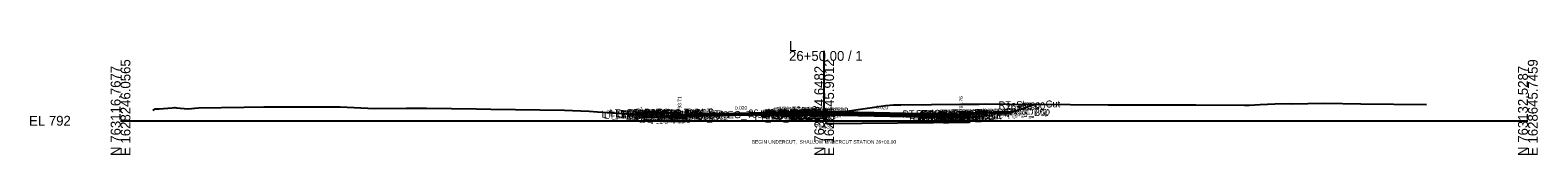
# Model space of a CAD drawing. Extents: x -26 to 4403, y -510 to 9556.
# Drawn here: x 974.3 to 1402.8, y 6490.3 to 6522.6 of the extents above; entities that cross this region are included whole.
import ezdxf

# ---------------------------------------------------------------- set-up
doc = ezdxf.new("R2010")
doc.units = 0
for name, color, linetype in [('Default', 7, 'Continuous'), ('Exist CMT Pavement', 7, 'Continuous'), ('Exist Cross Section Cell', 7, 'Continuous'), ('Exist XS Center Line Elevation Label', 7, 'Continuous'), ('Exist XS Ground Line', 7, 'Continuous'), ('Prop CMT Conc Surface', 7, 'Continuous'), ('Prop CMT Concrete Structures', 7, 'Continuous'), ('Prop CMT Pvmt Course 1', 7, 'Continuous'), ('Prop CMT Pvmt Course 1 CG', 7, 'Continuous'), ('Prop CMT Pvmt Course 1 Wedge', 7, 'Continuous'), ('Prop CMT Pvmt Course 2', 7, 'Continuous'), ('Prop CMT Pvmt Course 2 Wedge', 7, 'Continuous'), ('Prop CMT Pvmt Course 3', 7, 'Continuous'), ('Prop CMT Pvmt Course 3 Wedge', 7, 'Continuous'), ('Prop CMT Pvmt Surface', 7, 'Continuous'), ('Prop CMT Pvmt Wedge Surface 1', 7, 'Continuous'), ('Prop CMT Pvmt Wedge Surface 2', 7, 'Continuous'), ('Prop CMT Pvmt Wedge Surface 3', 7, 'Continuous'), ('Prop CMT Shallow Undercut', 7, 'Continuous'), ('Prop CMT Shallow Undercut Boundary', 7, 'Continuous'), ('Prop CMT Slope Grass', 7, 'Continuous'), ('Prop CMT Subgrade Earthwork', 7, 'Continuous'), ('Prop CMT Undercut Boundary', 7, 'Continuous'), ('Prop XS Hydro Elevations', 7, 'Continuous'), ('Prop XS SE Text', 7, 'Continuous'), ('Prop XS Side Slope Text', 7, 'Continuous'), ('Prop XSC Text', 7, 'Continuous'), ('Scratch_Level_0', 7, 'Continuous')]:
    doc.layers.add(name, color=color, linetype=linetype)

msp = doc.modelspace()

# ---------------------------------------------------------------- linework, layer by layer
at = {"layer": 'Exist CMT Pavement'}
msp.add_lwpolyline([(1160.9, 6501.43), (1171.19, 6501.86), (1176.98, 6501.75), (1181.31, 6501.69), (1185.62, 6501.51), (1189.99, 6501.34), (1190.57, 6501.32)], dxfattribs=at)
at = {"layer": 'Exist Cross Section Cell'}
for p, q in [((1200, 6500), (1200, 6519.84)), ((1000, 6500), (1200, 6500)), ((1200, 6500), (1400, 6500))]:
    msp.add_line(p, q, dxfattribs=at)
at = {"layer": 'Exist XS Ground Line'}
msp.add_lwpolyline([(1009.14, 6503.05), (1009.88, 6503.44), (1010.97, 6503.42), (1014.63, 6503.65), (1015.4, 6503.76), (1015.95, 6503.72), (1019.13, 6503.42), (1022.12, 6503.7), (1035.13, 6503.85), (1040.71, 6504.01), (1057.75, 6504.01), (1060.01, 6504), (1062.44, 6503.92), (1072.29, 6503.51), (1081.25, 6503.56), (1082.14, 6503.59), (1086.94, 6503.54), (1101.16, 6503.37), (1105.24, 6503.3), (1126.19, 6503.01), (1128.43, 6502.93), (1133.2, 6502.71), (1135.52, 6502.55), (1146.59, 6501.77), (1149.27, 6501.42), (1149.72, 6500.98), (1158.89, 6501.34), (1171.19, 6501.86), (1176.98, 6501.75), (1181.31, 6501.69), (1185.62, 6501.51), (1189.99, 6501.34), (1190.57, 6501.32), (1192.61, 6501.05), (1193.25, 6501.57), (1198.86, 6502.27), (1199.46, 6502.35), (1200, 6502.35), (1204.46, 6502.35), (1205.75, 6502.6), (1217.56, 6504.35), (1219.69, 6504.53), (1221.74, 6504.54), (1239.22, 6504.74), (1241.76, 6504.75), (1242.36, 6504.75), (1244.05, 6504.76), (1245.79, 6504.77), (1257.7, 6504.62), (1259.18, 6504.69), (1280.69, 6504.57), (1282.01, 6504.57), (1300, 6504.53), (1301.33, 6504.53), (1305.67, 6504.51), (1319.5, 6504.44), (1320.84, 6504.43), (1323.87, 6504.61), (1328.1, 6504.78), (1332.19, 6504.89), (1332.7, 6504.83), (1342.22, 6504.96), (1352.54, 6504.84), (1371.16, 6504.62)], dxfattribs=at)
at = {"layer": 'Prop CMT Conc Surface'}
for points in [[(1154.38, 6502.3), (1149.38, 6502.4)], [(1154.38, 6502.3), (1154.38, 6502.3)], [(1158.89, 6501.71), (1158.89, 6502.21), (1158.39, 6502.21)], [(1160.89, 6501.83), (1158.89, 6501.71)], [(1236.89, 6501.88), (1238.89, 6501.76)], [(1238.89, 6501.76), (1238.89, 6502.26), (1239.39, 6502.26)], [(1248.02, 6502.44), (1253.01, 6502.54)]]:
    msp.add_lwpolyline(points, dxfattribs=at)
at = {"layer": 'Prop CMT Concrete Structures'}
for points in [[(1149.38, 6502.4), (1154.38, 6502.3)], [(1149.38, 6502.07), (1149.38, 6502.4)], [(1154.38, 6501.97), (1149.38, 6502.07)], [(1154.38, 6502.3), (1154.38, 6502.3)], [(1160.89, 6501.83), (1158.89, 6501.71), (1158.89, 6502.21), (1158.39, 6502.21)], [(1158.39, 6502.21), (1158.39, 6501.2), (1160.89, 6501.25)], [(1160.89, 6501.25), (1160.89, 6501.83)], [(1196, 6502.7), (1195.99, 6502.86), (1195.24, 6503.11), (1194, 6503.14), (1192.76, 6502.87), (1192.01, 6502.62), (1192, 6502.46)], [(1192, 6502.46), (1196, 6502.7)], [(1236.89, 6501.88), (1238.89, 6501.76), (1238.89, 6502.26), (1239.39, 6502.26)], [(1239.39, 6502.26), (1239.39, 6501.24), (1236.89, 6501.29)], [(1236.89, 6501.29), (1236.89, 6501.88)], [(1253.01, 6502.54), (1248.02, 6502.44)], [(1248.02, 6502.44), (1248.02, 6502.11)], [(1248.02, 6502.11), (1253.01, 6502.21)], [(1253.01, 6502.21), (1253.01, 6502.54)]]:
    msp.add_lwpolyline(points, dxfattribs=at)
msp.add_lwpolyline([(1154.38, 6502.3), (1154.38, 6501.97), (1154.38, 6501.97)], close=True, dxfattribs=at)
at = {"layer": 'Prop CMT Pvmt Course 1'}
for points in [[(1192, 6502.46), (1160.89, 6501.83)], [(1160.89, 6501.71), (1192, 6502.33)], [(1160.89, 6501.83), (1160.89, 6501.58)], [(1160.89, 6501.58), (1160.89, 6501.71)], [(1160.89, 6501.58), (1160.89, 6501.58)], [(1192, 6502.46), (1196, 6502.7)], [(1192, 6502.21), (1192, 6502.46)], [(1192, 6502.21), (1192, 6502.46)], [(1196, 6502.45), (1192, 6502.21)], [(1192, 6502.33), (1192, 6502.21), (1192, 6502.21)], [(1196, 6502.7), (1196, 6502.45)], [(1196, 6502.7), (1236.89, 6501.88)], [(1196, 6502.45), (1196, 6502.7)], [(1236.89, 6501.63), (1196, 6502.45)], [(1236.89, 6501.88), (1236.89, 6501.63)]]:
    msp.add_lwpolyline(points, dxfattribs=at)
msp.add_lwpolyline([(1196, 6502.45), (1196, 6502.57), (1196, 6502.57), (1196, 6502.45)], close=True, dxfattribs=at)
at = {"layer": 'Prop CMT Pvmt Course 1 CG'}
for points in [[(1160.89, 6501.25), (1157.89, 6501.19), (1157.55, 6500.85)], [(1157.55, 6500.85), (1160.89, 6500.92)], [(1160.89, 6500.92), (1160.89, 6501.25)], [(1236.89, 6501.29), (1239.89, 6501.23), (1240.23, 6500.89)], [(1236.89, 6500.96), (1236.89, 6501.29)], [(1240.23, 6500.89), (1236.89, 6500.96)]]:
    msp.add_lwpolyline(points, dxfattribs=at)
at = {"layer": 'Prop CMT Pvmt Course 1 Wedge'}
for points in [[(1160.89, 6501.71), (1171.19, 6501.91), (1176.98, 6502.03), (1181.31, 6502.12), (1185.62, 6502.2), (1189.99, 6502.29), (1190.57, 6502.3), (1190.7, 6502.3), (1192, 6502.33)], [(1192, 6502.21), (1190.7, 6502.18), (1190.57, 6502.18), (1189.99, 6502.16), (1185.62, 6502.08), (1181.31, 6501.99), (1176.98, 6501.9), (1173.05, 6501.83), (1171.19, 6501.86), (1167.98, 6501.72), (1160.89, 6501.58)], [(1160.89, 6501.58), (1160.89, 6501.71)], [(1192, 6502.33), (1192, 6502.21)]]:
    msp.add_lwpolyline(points, dxfattribs=at)
at = {"layer": 'Prop CMT Pvmt Course 2'}
for points in [[(1160.89, 6501.25), (1160.89, 6501.58)], [(1160.89, 6501.58), (1160.89, 6501.58)], [(1160.89, 6501.58), (1160.89, 6501.25)], [(1160.89, 6501.25), (1160.89, 6501.25)], [(1192, 6502.21), (1196, 6502.45)], [(1192, 6501.87), (1192, 6502.21)], [(1196, 6502.11), (1192, 6501.87)], [(1196, 6502.45), (1196, 6502.11)], [(1196, 6502.11), (1196, 6502.45)], [(1196, 6502.45), (1236.89, 6501.63)], [(1236.89, 6501.29), (1196, 6502.11)], [(1236.89, 6501.63), (1236.89, 6501.29)]]:
    msp.add_lwpolyline(points, dxfattribs=at)
at = {"layer": 'Prop CMT Pvmt Course 2 Wedge'}
for points in [[(1160.89, 6501.58), (1167.98, 6501.72)], [(1167.98, 6501.72), (1160.89, 6501.43)], [(1160.89, 6501.43), (1160.89, 6501.58)], [(1173.05, 6501.83), (1176.98, 6501.9)], [(1192, 6501.87), (1190.7, 6501.85), (1190.57, 6501.84), (1189.99, 6501.83), (1185.62, 6501.74), (1181.81, 6501.67), (1181.31, 6501.69), (1176.98, 6501.75), (1173.05, 6501.83)], [(1176.98, 6501.9), (1181.31, 6501.99), (1185.62, 6502.08), (1189.99, 6502.16), (1190.57, 6502.18), (1190.7, 6502.18), (1192, 6502.21)], [(1192, 6502.21), (1192, 6501.87)]]:
    msp.add_lwpolyline(points, dxfattribs=at)
at = {"layer": 'Prop CMT Pvmt Course 3'}
for points in [[(1160.89, 6501.25), (1160.89, 6501.25)], [(1160.89, 6501.25), (1160.89, 6500.92)], [(1160.89, 6500.92), (1160.89, 6501.25)], [(1160.89, 6500.92), (1160.89, 6500.92)], [(1192, 6501.87), (1196, 6502.11)], [(1192, 6501.54), (1192, 6501.87)], [(1196, 6501.78), (1192, 6501.54)], [(1196, 6502.11), (1196, 6501.78)], [(1196, 6502.11), (1236.89, 6501.29)], [(1196, 6501.78), (1196, 6502.11)], [(1236.89, 6500.96), (1196, 6501.78)], [(1236.89, 6500.96), (1196, 6501.78)], [(1236.89, 6500.96), (1196, 6501.78)], [(1236.89, 6501.29), (1236.89, 6500.96)]]:
    msp.add_lwpolyline(points, dxfattribs=at)
at = {"layer": 'Prop CMT Pvmt Course 3 Wedge'}
for points in [[(1181.8, 6501.67), (1185.62, 6501.74)], [(1192, 6501.13), (1190.7, 6501.31), (1190.57, 6501.32), (1189.99, 6501.34), (1185.62, 6501.51), (1181.8, 6501.67)], [(1185.62, 6501.74), (1189.99, 6501.83), (1190.57, 6501.84), (1190.7, 6501.85), (1192, 6501.87)]]:
    msp.add_lwpolyline(points, dxfattribs=at)
at = {"layer": 'Prop CMT Pvmt Surface'}
for points in [[(1192, 6502.46), (1160.89, 6501.83)], [(1192, 6502.46), (1196, 6502.7)], [(1196, 6502.7), (1236.89, 6501.88)]]:
    msp.add_lwpolyline(points, dxfattribs=at)
at = {"layer": 'Prop CMT Pvmt Wedge Surface 1'}
for points in [[(1192, 6502.33), (1160.89, 6501.71)], [(1160.89, 6501.58), (1160.89, 6501.83)], [(1160.89, 6501.71), (1160.89, 6501.58)], [(1160.89, 6501.58), (1160.89, 6501.58)], [(1192, 6502.46), (1192, 6502.21), (1192, 6502.21), (1192, 6502.33)]]:
    msp.add_lwpolyline(points, dxfattribs=at)
at = {"layer": 'Prop CMT Pvmt Wedge Surface 2'}
for points in [[(1192, 6502.21), (1160.89, 6501.58)], [(1160.89, 6501.58), (1160.89, 6501.83)], [(1192, 6502.46), (1192, 6502.21)]]:
    msp.add_lwpolyline(points, dxfattribs=at)
at = {"layer": 'Prop CMT Pvmt Wedge Surface 3'}
for points in [[(1192, 6501.87), (1160.89, 6501.25)], [(1160.89, 6501.25), (1160.89, 6501.83)], [(1192, 6502.46), (1192, 6501.87)]]:
    msp.add_lwpolyline(points, dxfattribs=at)
at = {"layer": 'Prop CMT Shallow Undercut'}
for points in [[(1156.55, 6500.83), (1156.55, 6499.83), (1160.87, 6499.92), (1160.9, 6500.92)], [(1190.57, 6501.32), (1190.57, 6500.51), (1192.04, 6500.54), (1195.91, 6500.77), (1200.57, 6500.69), (1200.57, 6501.69), (1196, 6501.78), (1193.97, 6501.66), (1193.25, 6501.57), (1192.61, 6501.05)]]:
    msp.add_lwpolyline(points, close=True, dxfattribs=at)
at = {"layer": 'Prop CMT Shallow Undercut Boundary'}
for points in [[(1156.55, 6500.83), (1156.55, 6499.83), (1160.9, 6499.92), (1160.9, 6500.92)], [(1190.57, 6501.32), (1190.57, 6500.51), (1192.04, 6500.54), (1196.02, 6500.78), (1200.57, 6500.69), (1200.57, 6501.69), (1196, 6501.78), (1193.97, 6501.66), (1193.25, 6501.57), (1192.61, 6501.05)]]:
    msp.add_lwpolyline(points, close=True, dxfattribs=at)
at = {"layer": 'Prop CMT Slope Grass'}
for points in [[(1158.39, 6502.21), (1148.87, 6502.4), (1146.86, 6501.74)], [(1239.39, 6502.26), (1253.01, 6502.53)], [(1253.01, 6502.53), (1253.54, 6502.54), (1259.97, 6504.68)]]:
    msp.add_lwpolyline(points, dxfattribs=at)
at = {"layer": 'Prop CMT Subgrade Earthwork'}
msp.add_line((1190.57, 6501.51), (1190.57, 6501.32), dxfattribs=at)
for points in [[(1160.89, 6500.92), (1157.55, 6500.85), (1156.14, 6502.26)], [(1160.89, 6500.92), (1160.9, 6501.43)], [(1160.89, 6500.92), (1160.89, 6500.92)], [(1190.57, 6501.51), (1190.7, 6501.51), (1192, 6501.54)], [(1192, 6501.54), (1196, 6501.78)], [(1196, 6501.78), (1236.89, 6500.96)], [(1196, 6501.78), (1236.89, 6500.96)], [(1196, 6501.78), (1236.89, 6500.96)], [(1236.89, 6500.96), (1240.23, 6500.89), (1241.64, 6502.3)]]:
    msp.add_lwpolyline(points, dxfattribs=at)
at = {"layer": 'Prop CMT Undercut Boundary'}
msp.add_lwpolyline([(1200.57, 6501.69), (1200.57, 6499.25), (1241.23, 6499.59), (1241.23, 6500.87)], close=True, dxfattribs=at)

# ---------------------------------------------------------------- texts
at = {"layer": 'Default'}
msp.add_text('-', height=0.0001, dxfattribs=at).set_placement((1000, 6500))
at = {"layer": 'Exist Cross Section Cell'}
for s, p in [('L', (1190, 6519.84)), ('26+50.00 / 1', (1190, 6517.04)), ('EL 792', (974, 6498.6))]:
    msp.add_text(s, height=2.8, dxfattribs=at).set_placement(p)
for s, p in [('N 763116.7677', (1000, 6490)), ('E 1628246.0565', (1002.8, 6490)), ('N 763124.6482', (1200, 6490)), ('E 1628445.9012', (1202.8, 6490)), ('N 763132.5287', (1400, 6490)), ('E 1628645.7459', (1402.8, 6490))]:
    msp.add_text(s, height=2.8, rotation=90, dxfattribs=at).set_placement(p)
at = {"layer": 'Exist XS Center Line Elevation Label'}
msp.add_text('794.35', height=1.2, dxfattribs=at).set_placement((1197.44, 6497.75))
at = {"layer": 'Prop XS Hydro Elevations'}
for s, p in [('793.71', (1159.39, 6502.71)), ('793.76', (1239.39, 6502.76))]:
    msp.add_text(s, height=1, rotation=90, dxfattribs=at).set_placement(p)
at = {"layer": 'Prop XS SE Text'}
for rotation, p in [(1.1453, (1174.67, 6503.11)), (358.8553, (1214.71, 6503.32))]:
    msp.add_text('0.020', height=1, rotation=rotation, dxfattribs=at).set_placement(p)
at = {"layer": 'Prop XS Side Slope Text'}
for rotation, p in [(18.4349, (1255.38, 6503.72)), (18.4473, (1146.87, 6502.53))]:
    msp.add_text('3:1', height=1, rotation=rotation, dxfattribs=at).set_placement(p)
at = {"layer": 'Prop XSC Text'}
msp.add_text('BEGIN UNDERCUT,  SHALLOW UNDERCUT STATION 26+00.00', height=1, dxfattribs=at).set_placement((1179.43, 6493.5))
at = {"layer": 'Scratch_Level_0'}
for s, p in [('RT_Slope_Cut', (1249.58, 6503.48)), ('26+50.00', (1251.59, 6503.02)), ('LT_Sub_Trench_Out_DLT', (1136.73, 6500.87)), ('LT_Slope_Fill', (1137.4, 6500.55)), ('LT_CSLP_Pnt', (1139.06, 6501.21)), ('LT_SDWK_Out_Top', (1140.64, 6501.03)), ('LT_SDWK_Out_Bot', (1140.67, 6500.7)), ('LT_SDWK_In_Top', (1142.26, 6501.06)), ('LT_SDWK_In_Bot', (1142.29, 6500.73)), ('LT_CG1_Shelf_Out', (1144.46, 6499.92)), ('26+50.00', (1144.59, 6501.22)), ('LT_PV_Sub_Tie_Out', (1145.87, 6500.13)), ('LT_CG_Top_Face', (1146.17, 6500.96)), ('LT_CG_Top_BOC', (1146.69, 6500.98)), ('LT_CG_Bot_BOC', (1146.72, 6499.97)), ('LT_CG_Top_Gut', (1147.15, 6500.48)), ('LT_Sub_OEOP', (1147.68, 6499.65)), ('LT_Sub_OEOT_CG', (1148.28, 6499.66)), ('LT_PV_OEEOP_EG', (1148.45, 6500.18)), ('LT_Sub_OEEOP', (1150.12, 6499.7)), ('LT_PV2_OEEOP', (1150.22, 6500.37)), ('LT_PV3_OEEOP', (1150.22, 6500.04)), ('LT_PV1_OEEOP', (1150.78, 6500.51)), ('LT_CG_Bot_IE', (1150.82, 6500.05)), ('LT_Sub_OEOT', (1150.99, 6499.72)), ('LT_PV2_OEOT', (1151.08, 6500.39)), ('LT_PV3_OEOT', (1151.08, 6500.05)), ('LT_PV1_OEOT', (1151.65, 6500.65)), ('26+50.00', (1151.95, 6501.08)), ('LT_PV_EG_TestPt', (1162.88, 6500.49)), ('26+50.00', (1178.43, 6501.18)), ('LT_PV_IEEOP_EG', (1180.21, 6499.89)), ('LT_PV2_IEEOP', (1181.97, 6501)), ('LT_PV3_IEEOP', (1181.97, 6500.67)), ('LT_PV1_IEEOP', (1182.54, 6501.14)), ('LT_PV2_PGL1', (1182.9, 6501.02)), ('LT_PV3_PGL1', (1182.9, 6500.69)), ('LT_PV2_PGL', (1183.23, 6501.03)), ('LT_PV3_PGL', (1183.23, 6500.7)), ('LT_PV4_PGL', (1183.23, 6500.36)), ('LT_PV1_PGL', (1183.8, 6501.29)), ('MI_Face In', (1183.92, 6501.46)), ('26+50.00', (1185.22, 6501.33)), ('RT_Sub_OEEOP', (1185.19, 6500.56)), ('RT_PV2_OEEOP', (1185.28, 6501.23)), ('RT_PV3_OEEOP', (1185.28, 6500.9)), ('MI_Top In', (1185.63, 6501.73)), ('26+50.00', (1185.89, 6501.71)), ('RT_PV1_OEEOP', (1185.85, 6501.37)), ('RT_PV2_IEEOP', (1185.93, 6501.24)), ('MI_Face Out', (1186.28, 6501.67)), ('MI_Top Out', (1186.49, 6501.94)), ('RT_PV1_IEEOP', (1186.49, 6501.38)), ('RT_PV2_PGL1', (1186.86, 6501.26)), ('RT_PV3_PGL1', (1186.86, 6500.93)), ('MI_Crown', (1187.09, 6502)), ('RT_PV2_PGL', (1187.19, 6501.27)), ('RT_PV4_PGL', (1187.19, 6500.6)), ('MI_Bot Out', (1187.28, 6501.52)), ('RT_PV1_PGL', (1187.75, 6501.53)), ('26+50.00', (1188.93, 6501.82)), ('26+50.00', (1189.21, 6501.67)), ('RT_Sub_Trench_Out_DLT', (1222.18, 6500.91)), ('RT_Sub_OEOT_CG', (1224.23, 6499.71)), ('RT_CG_Top_Face', (1226.12, 6501)), ('RT_CG1_Shelf_Out', (1226.41, 6499.96)), ('RT_CG_Bot_IE', (1226.78, 6500.09)), ('RT_Sub_OEOT', (1226.94, 6499.76)), ('RT_PV2_OEOT', (1227.04, 6500.43)), ('RT_PV3_OEOT', (1227.04, 6500.1)), ('RT_CG_Top_Gut', (1227.1, 6500.52)), ('RT_PV1_OEOT', (1227.6, 6500.69)), ('RT_CG_Top_BOC', (1227.65, 6501.02)), ('RT_CG_Bot_BOC', (1227.68, 6500.01)), ('RT_Sub_OEOP', (1230.31, 6499.7)), ('26+50.00', (1230.88, 6500.7)), ('26+50.00', (1232.11, 6500.89)), ('26+50.00', (1232.44, 6501.12)), ('26+50.00', (1233.76, 6501.15)), ('RT_SDWK_In_Top', (1235.85, 6501.2)), ('RT_SDWK_In_Bot', (1235.88, 6500.86)), ('26+50.00', (1238.71, 6501.25)), ('RT_SDWK_Out_Top', (1239.23, 6501.26)), ('RT_SDWK_Out_Bot', (1239.26, 6500.93)), ('RT_Shld_O', (1245.57, 6501.38)), ('26+50.00', (1246.42, 6501.4)), ('CSLP_Pnt', (1246.42, 6501.4))]:
    msp.add_text(s, height=2, rotation=1.1458, dxfattribs=at).set_placement(p)

doc.saveas('drawing.dxf')
